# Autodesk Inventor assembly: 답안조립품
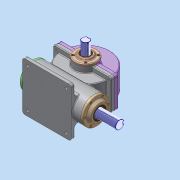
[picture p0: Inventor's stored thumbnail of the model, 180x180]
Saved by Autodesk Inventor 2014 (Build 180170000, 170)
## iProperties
Created: 2023-12
Part Number: 답안조립품
Document SubType Name: Assembly
Designer: dg
Mass: 21921.6 g
Surface Area: 7843.92 cm^2
Volume: 4928.8 cm^3
Density: 4.44767 g/cm^3
Author: dg
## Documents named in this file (14)
- C:\Users\dg\Desktop\631208V1003\답안조립품.iam
- C:\Users\dg\Desktop\631208V1003\본체.ipt
- C:\Users\dg\Desktop\631208V1003\깊은 홈 볼 베어링 6206.ipt
- C:\Users\dg\Desktop\631208V1003\깊은 홈 볼 베어링 6209.ipt
- C:\Users\dg\Desktop\631208V1003\뒤커버.ipt
- C:\Users\dg\Desktop\631208V1003\본체 커버.ipt
- C:\Users\dg\Desktop\631208V1003\서브커버.ipt
- C:\Users\dg\Desktop\631208V1003\앞커버.ipt
- C:\Users\dg\Desktop\631208V1003\오일 실 30 42 7.ipt
- C:\Users\dg\Desktop\631208V1003\오일 실 35 55 11.ipt
- C:\Users\dg\Desktop\631208V1003\웜 샤프트.ipt
- C:\Users\dg\Desktop\631208V1003\웜 휠.ipt
- C:\Users\dg\Desktop\631208V1003\육각 소켓 머리 볼트 M5 x 12.ipt
- C:\Users\dg\Desktop\631208V1003\육각 소켓 머리 볼트 M6 x 20.ipt
